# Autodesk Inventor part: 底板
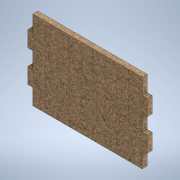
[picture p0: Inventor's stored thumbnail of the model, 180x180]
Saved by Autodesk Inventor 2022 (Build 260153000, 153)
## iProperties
Created: 2024-11
Part Number: 底板
Material: MDF 中密度繊維ボード
Document SubType Name: Modeling
Designer: shimizu
Density: 0.8 g/cm^3
Appearance: ダンボール - 段ボール紙
Author: shimizu
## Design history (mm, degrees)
sketch "スケッチ1"
  geometry: L1 (-25.119, 10.226)-(29.881, 10.226); L2 (29.881, -29.774)-(-25.119, -29.774); L3 (-25.119, 2.226)-(-27.619, 2.226); L4 (-27.619, 2.226)-(-27.619, -5.774); L5 (-27.619, -5.774)-(-25.119, -5.774); L6 (-25.119, -13.774)-(-27.619, -13.774); L7 (-27.619, -13.774)-(-27.619, -21.774); L8 (-27.619, -21.774)-(-25.119, -21.774); L9 (29.881, 2.226)-(32.381, 2.226); L10 (32.381, 2.226)-(32.381, -5.774); L11 (32.381, -5.774)-(29.881, -5.774); L12 (29.881, -13.774)-(32.381, -13.774); L13 (32.381, -13.774)-(32.381, -21.774); L14 (32.381, -21.774)-(29.881, -21.774); L15 (-25.119, 2.226)-(-25.119, 10.226); L16 (-25.119, -29.774)-(-25.119, -21.774); L17 (-25.119, -13.774)-(-25.119, -5.774); L18 (29.881, 10.226)-(29.881, 2.226); L19 (29.881, -5.774)-(29.881, -13.774); L20 (29.881, -21.774)-(29.881, -29.774); 1 further point
  constraints: 40 end point, 14 parallel, 7 perpendicular, 5 horizontal
  dimensions: "d16" = 60 distance between parallel lines of L13 L7
extrude "押し出し1" new body sketch "スケッチ1" distance "d2" = 2.5; taper "d3" = 0 deg
node "ソリッド1"
